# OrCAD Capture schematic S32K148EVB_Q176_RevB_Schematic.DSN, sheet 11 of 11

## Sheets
11 09. I/O HEADERS: size D; company: Freescale Semiconductor; note: SCH-29642 PDF: SPF-29642
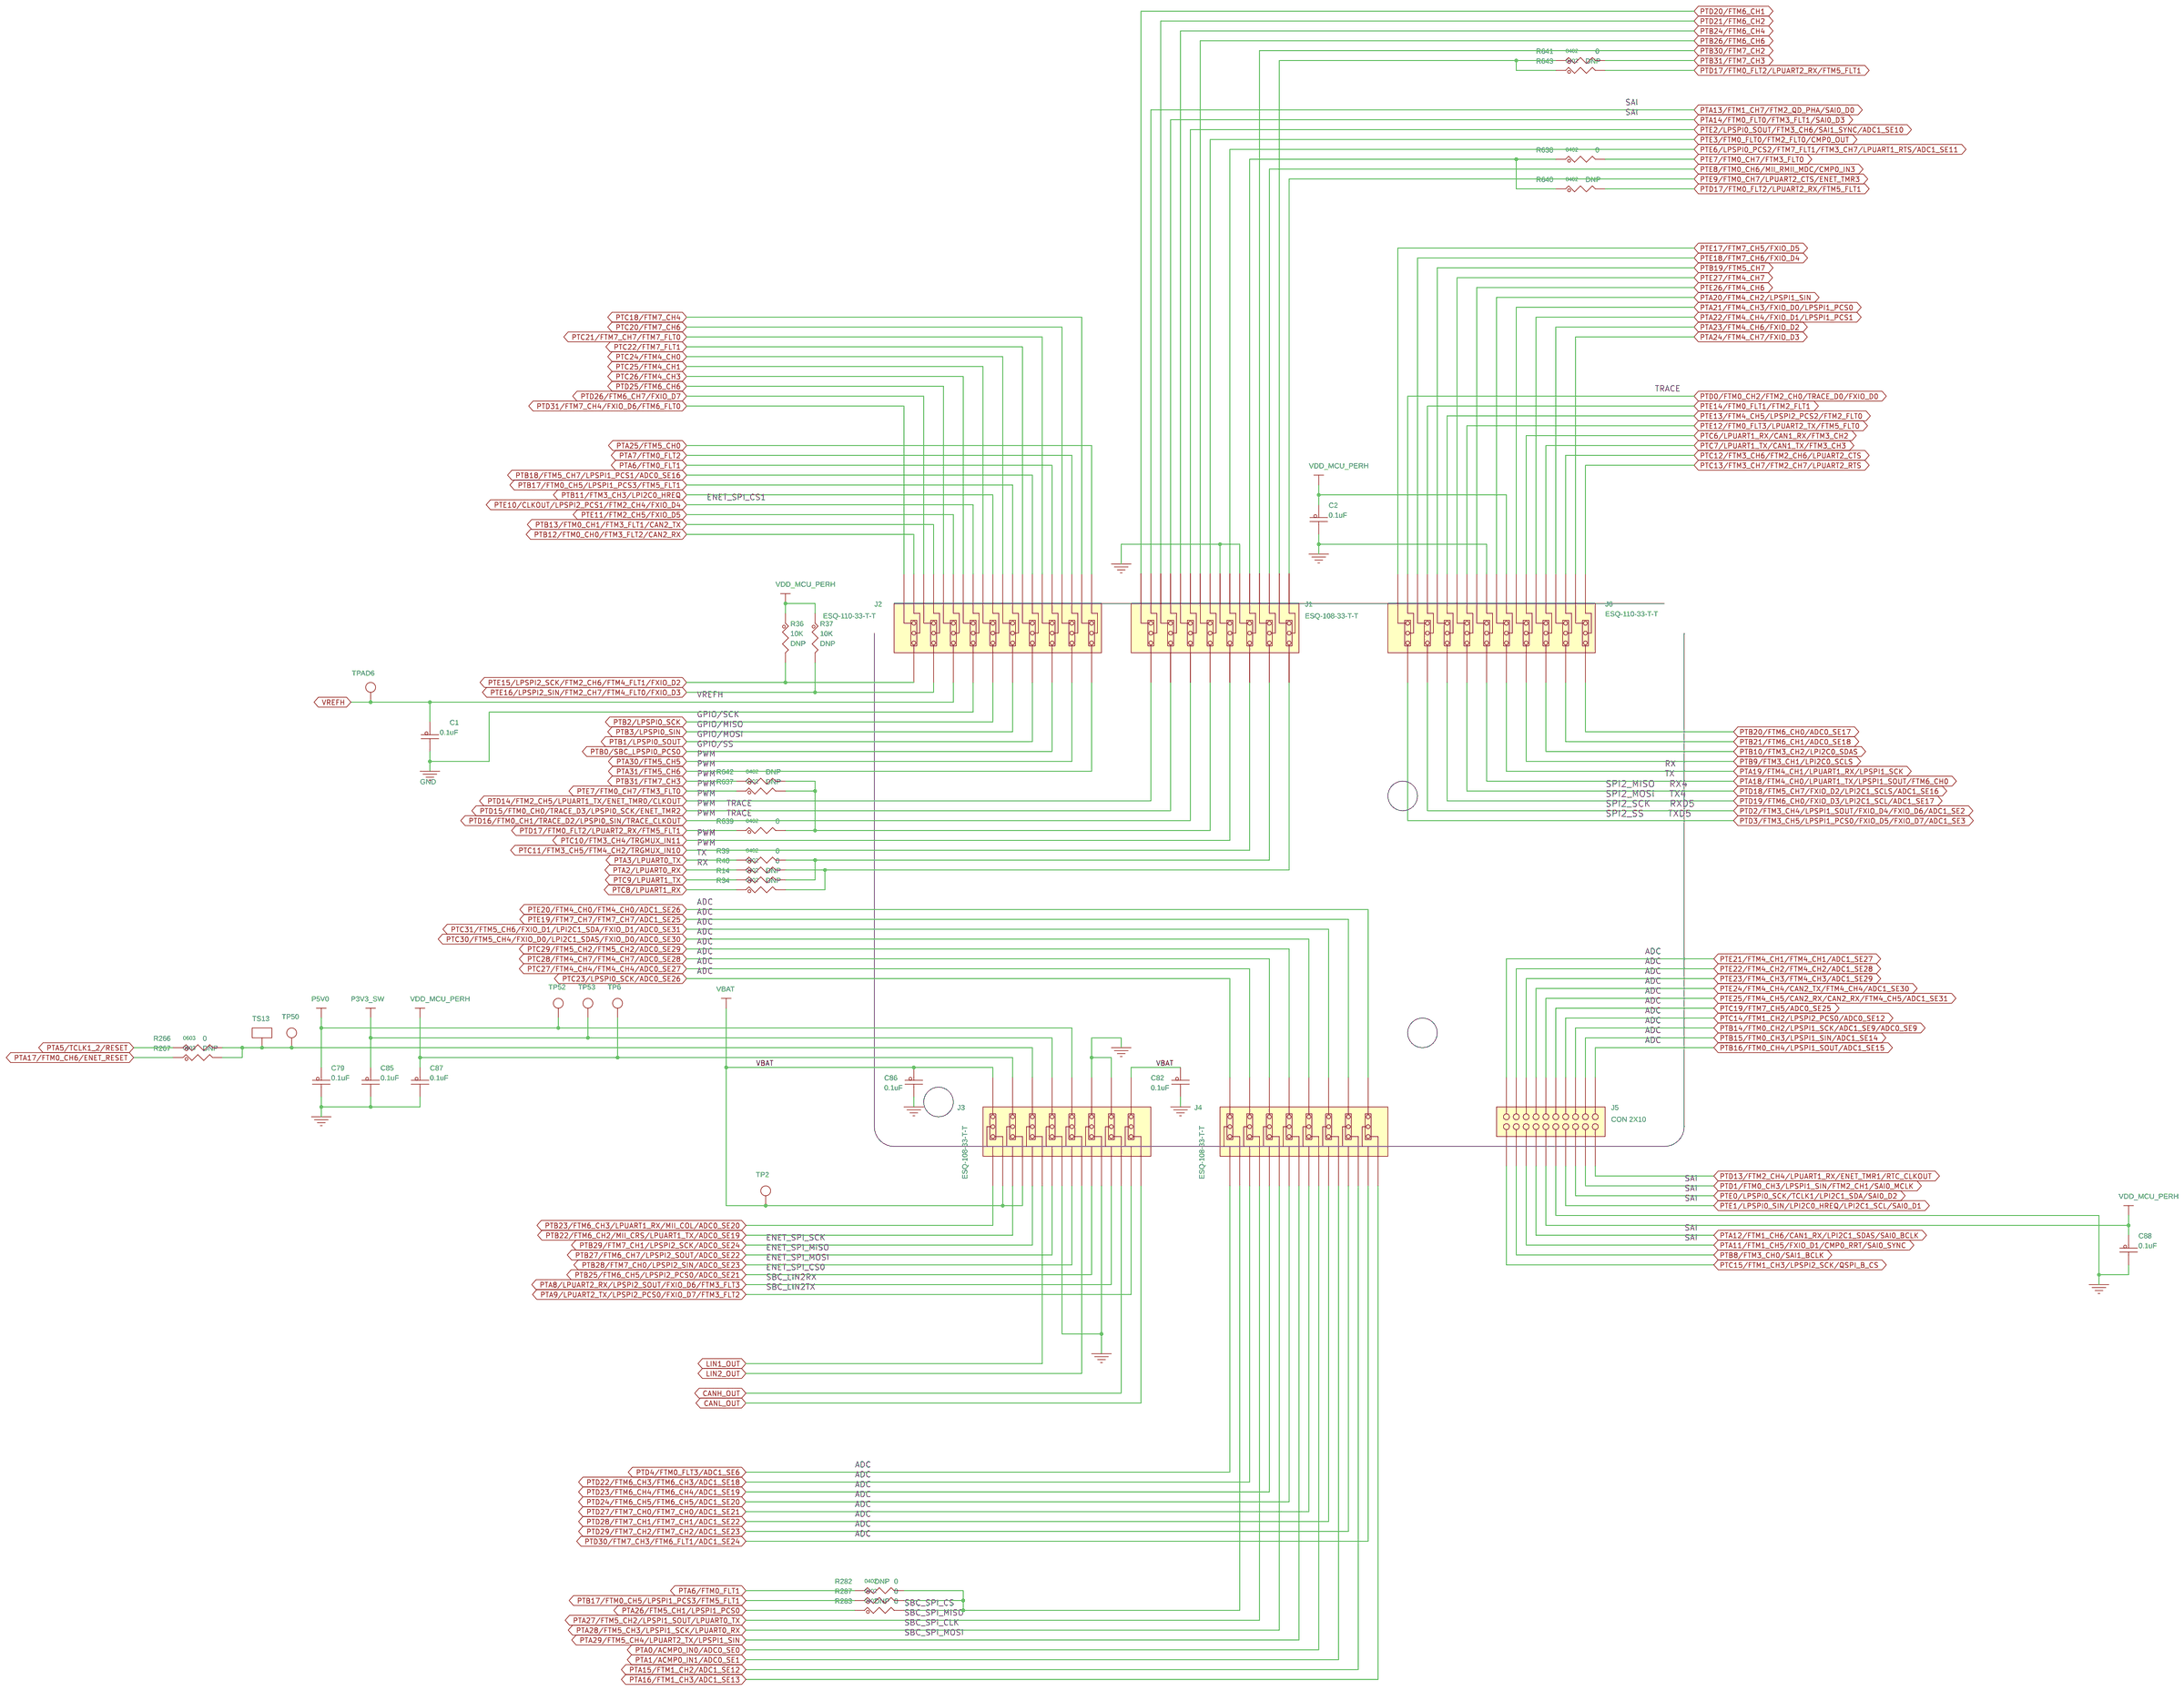
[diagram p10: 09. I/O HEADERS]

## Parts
C1  0.1uF  [CC0402_25]
C2  0.1uF  [CC0402_25]
C79  0.1uF  [CC0402_25]
C82  0.1uF  [CC0402_25]
C85  0.1uF  [CC0402_25]
C86  0.1uF  [CC0402_25]
C87  0.1uF  [CC0402_25]
C88  0.1uF  [CC0402_25]
J1  ESQ-108-33-T-T  [con_3x8_100_th]
J2  ESQ-110-33-T-T  [con_3x10_100_th]
J3  ESQ-108-33-T-T  [con_3x8_100_th]
J4  ESQ-108-33-T-T  [con_3x8_100_th]
J5  CON 2X10  [hdr210_esq_skt]
J6  ESQ-110-33-T-T  [con_3x10_100_th]
R14  0  [RC0402_25]
R34  0  [RC0402_25]
R36  10K  [RC0603_OV]
R37  10K  [RC0603_OV]
R39  0  [RC0402_25]
R40  0  [RC0402_25]
R266  0  [RC0603]
R267  0  [RC0603]
R282  0  [RC0402_25]
R283  0  [RC0402_25]
R287  0  [RC0402_25]
R637  0  [RC0402_25]
R638  0  [RC0402_25]
R639  0  [RC0402_25]
R640  0  [RC0402_25]
R641  0  [RC0402_25]
R642  0  [RC0402_25]
R643  0  [RC0402_25]
TP2  TPAD_028  [TPAD_028]
TP6  TPAD_028  [TPAD_028]
TP50  TPAD_028  [TPAD_028]
TP52  TPAD_028  [TPAD_028]
TP53  TPAD_028  [TPAD_028]
TPAD6  TPAD_030  [TPAD_030]
TS13  TESTLOOP  [testpoint_135_070mil]

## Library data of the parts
C1 C2 C79 C82 C85-C88 = CAP_NP: CAP CER 0.1uF 50V 10% X7R 0402; AGILE_PN: 150-79069; CAD_APPROVED: Yes; FPLIST: CC0402_25,CC0402_HD,0402_CC; HEIGHT: 0.55MM; MFG_NAME01: MURATA; MFG_PN01: GRM155R71H104KE14D; ROHS: Yes; Tolerance: 10%; VOLTAGE: 50V
J1 J3 J4 = HDR-3X8_A: CON 3X8 SKT TH 100MIL CTR 640H SN 90L; AGILE_PN: 210-81399; CAD_APPROVED: Yes; HEIGHT: 16.256MM; MFG_NAME01: SAMTEC; ROHS: Yes; Temp_Range: -55C to +105C
J2 J6 = HDR-3X10_A: CON 3X10 SKT TH 100MIL CTR 640H SN 90L; AGILE_PN: 210-81402; CAD_APPROVED: Yes; HEIGHT: 16/256MM; MFG_NAME01: SAMTEC; ROHS: Yes; Temp_Range: -55C to +105C
J5 = CONN_HDR_10X2: CON 2X10 SKT TH 100MIL CTR 645H SN 90L; AGILE_PN: 210-81129; CAD_APPROVED: Yes; HEIGHT: 16.38 MM; MFG_NAME01: SAMTEC; MFG_PN01: ESQ-110-33-T-D; ROHS: Yes
R14 R34 R282 R283 R637 R640 R642 R643 = RES: RES MF ZERO OHM 1/16W -- AEC-Q200 0402; AGILE_PN: 470-80742; ASSY_OPT: DNP; CAD_APPROVED: Yes; FPLIST: RC0402_25,RC0402_HD,0402_CC; HEIGHT: 0.45 MM; MFG_NAME01: VISHAY INTERTECHNOLOGY; MFG_PN01: CRCW04020000Z0ED; PCKG: 0402; ROHS: Yes
R36 R37 = RES: RES MF 10K 1/10W 5% 0603; AGILE_PN: 470-75410; ASSY_OPT: DNP; CAD_APPROVED: Yes; FPLIST: RC0603_OV,RC0603,0603_CC; HEIGHT: 0.55MM; MFG_NAME01: BOURNS; MFG_PN01: CR0603-JW-103ELF; ROHS: Yes; Tolerance: 5%
R39 R40 R287 R638 R639 R641 = RES: RES MF ZERO OHM 1/16W -- AEC-Q200 0402; AGILE_PN: 470-80742; CAD_APPROVED: Yes; FPLIST: RC0402_25,RC0402_HD,0402_CC; HEIGHT: 0.45 MM; MFG_NAME01: VISHAY INTERTECHNOLOGY; MFG_PN01: CRCW04020000Z0ED; PCKG: 0402; ROHS: Yes
R266 = RES: RES MF ZERO OHM 1/10W -- AEC-Q200 0603; AGILE_PN: 470-75407; CAD_APPROVED: Yes; FPLIST: RC0603_OV,RC0603,R603-X2,0603_CC; HEIGHT: 0.6MM; MFG_NAME01: PANASONIC; MFG_PN01: ERJ-3GEY0R00V; PCKG: 0603; ROHS: Yes; Tolerance: 1%
R267 = RES: RES MF ZERO OHM 1/10W -- AEC-Q200 0603; AGILE_PN: 470-75407; ASSY_OPT: DNP; CAD_APPROVED: Yes; FPLIST: RC0603_OV,RC0603,R603-X2,0603_CC; HEIGHT: 0.6MM; MFG_NAME01: PANASONIC; MFG_PN01: ERJ-3GEY0R00V; PCKG: 0603; ROHS: Yes; Tolerance: 1%
TP2 TP6 TP50 TP52 TP53 = TESTLOOP: TEST POINT PAD 28MIL DIA SMT, NO PART TO ORDER; AGILE_PN: 211-79313; CAD_APPROVED: Yes; HEIGHT: 0.1 MM; MFG_NAME01: N/A; MFG_PN01: N/A; ROHS: Yes
TPAD6 = TestLoop: TEST POINT PAD 30MIL DIA SMT, NO PART TO ORDER; AGILE_PN: 211-76642; CAD_APPROVED: Yes; HEIGHT: 0.1MM; MFG_NAME01: NOTACOMPONENT; MFG_PN01: NOTACOMPONENT; ROHS: Yes
TS13 = TEST_POINT_4: TEST POINT PAD SIZE 3.4MM X 1.8MM SMT; AGILE_PN: 211-75906; CAD_APPROVED: Yes; HEIGHT: 1.53 MM; MFG_NAME01: KEYSTONE ELECTRONICS; MFG_PN01: 5015; PRIORITY_PN: 922-00014; ROHS: Yes

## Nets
GND: C1.2 C2.2 C79.2 C82.2 C85.2 C86.2 C87.2 C88.2 J1.9 J1.12 J2.19 J3.12 J3.16 J3.18 J3.19 J5.12 J6.17 ; also on sheet 1 2 3 4 5 6 7 8 9
P3V3_SW: C85.1 J3.10 TP53.1(Pin1) ; also on sheet 1 2 4 5 6 7
P5V0: C79.1 J3.13 TP52.1(Pin1) ; also on sheet 1 2 4 6 9
VBAT: C82.1 C86.1 J3.1 J3.3 J3.6 J3.22 TP2.1(Pin1) ; also on sheet 2
VDD_MCU_PERH: C2.1 C87.1 C88.1 J3.4 J5.10 J6.14 R36.1 R37.1 TP6.1(Pin1) ; also on sheet 2 3 4 6 9
CANH_OUT: J3.21 ; also on sheet 2
CANL_OUT: J3.24 ; also on sheet 2
LIN1_OUT: J3.9 ; also on sheet 2
LIN2_OUT: J3.15 ; also on sheet 2
PTA0/ACMP0_IN0/ADC0_SE0: J4.15 ; also on sheet 3
PTA1/ACMP0_IN1/ADC0_SE1: J4.18 ; also on sheet 3
PTA2/LPUART0_RX: R40.1 ; also on sheet 2 3
PTA3/LPUART0_TX: R39.1 ; also on sheet 2 3
PTA5/TCLK1_2/RESET: R266.1 ; also on sheet 2 3 4 5
PTA6/FTM0_FLT1: J2.8 R282.1 ; also on sheet 3
PTA7/FTM0_FLT2: J2.5 ; also on sheet 3
PTA8/LPUART2_RX/LPSPI2_SOUT/FXIO_D6/FTM3_FLT3: J3.20 ; also on sheet 2 3
PTA9/LPUART2_TX/LPSPI2_PCS0/FXIO_D7/FTM3_FLT2: J3.23 ; also on sheet 2 3
PTA11/FTM1_CH5/FXIO_D1/CMP0_RRT/SAI0_SYNC: J5.6 ; also on sheet 1 3
PTA12/FTM1_CH6/CAN1_RX/LPI2C1_SDAS/SAI0_BCLK: J5.8 ; also on sheet 1 3
PTA13/FTM1_CH7/FTM2_QD_PHA/SAI0_D0: J1.23 ; also on sheet 1 3
PTA14/FTM0_FLT0/FTM3_FLT1/SAI0_D3: J1.20 ; also on sheet 1 3
PTA15/FTM1_CH2/ADC1_SE12: J4.21 ; also on sheet 3
PTA16/FTM1_CH3/ADC1_SE13: J4.24 ; also on sheet 3
PTA17/FTM0_CH6/ENET_RESET: R267.1 ; also on sheet 3 4
PTA18/FTM4_CH0/LPUART1_TX/LPSPI1_SOUT/FTM6_CH0: J6.16 ; also on sheet 3
PTA19/FTM4_CH1/LPUART1_RX/LPSPI1_SCK: J6.13 ; also on sheet 3
PTA20/FTM4_CH2/LPSPI1_SIN: J6.15 ; also on sheet 3
PTA21/FTM4_CH3/FXIO_D0/LPSPI1_PCS0: J6.12 ; also on sheet 3
PTA22/FTM4_CH4/FXIO_D1/LPSPI1_PCS1: J6.9 ; also on sheet 3
PTA23/FTM4_CH6/FXIO_D2: J6.6 ; also on sheet 3
PTA24/FTM4_CH7/FXIO_D3: J6.3 ; also on sheet 3
PTA25/FTM5_CH0: J2.2 ; also on sheet 3 4
PTA26/FTM5_CH1/LPSPI1_PCS0: R283.1 ; also on sheet 2 3
PTA27/FTM5_CH2/LPSPI1_SOUT/LPUART0_TX: J4.6 ; also on sheet 2 3
PTA28/FTM5_CH3/LPSPI1_SCK/LPUART0_RX: J4.9 ; also on sheet 2 3
PTA29/FTM5_CH4/LPUART2_TX/LPSPI1_SIN: J4.12 ; also on sheet 2 3
PTA30/FTM5_CH5: J2.4 ; also on sheet 3
PTA31/FTM5_CH6: J2.1 ; also on sheet 3
PTB0/SBC_LPSPI0_PCS0: J2.7 ; also on sheet 3
PTB1/LPSPI0_SOUT: J2.10 ; also on sheet 3
PTB2/LPSPI0_SCK: J2.16 ; also on sheet 3
PTB3/LPSPI0_SIN: J2.13 ; also on sheet 3
PTB8/FTM3_CH0/SAI1_BCLK: J5.4 ; also on sheet 1 3
PTB9/FTM3_CH1/LPI2C0_SCLS: J6.10 ; also on sheet 1 3 6
PTB10/FTM3_CH2/LPI2C0_SDAS: J6.7 ; also on sheet 1 3 6
PTB11/FTM3_CH3/LPI2C0_HREQ: J2.17 ; also on sheet 3
PTB12/FTM0_CH0/FTM3_FLT2/CAN2_RX: J2.29 ; also on sheet 3
PTB13/FTM0_CH1/FTM3_FLT1/CAN2_TX: J2.26 ; also on sheet 3
PTB14/FTM0_CH2/LPSPI1_SCK/ADC1_SE9/ADC0_SE9: J5.15 ; also on sheet 3
PTB15/FTM0_CH3/LPSPI1_SIN/ADC1_SE14: J5.17 ; also on sheet 3
PTB16/FTM0_CH4/LPSPI1_SOUT/ADC1_SE15: J5.19 ; also on sheet 3
PTB17/FTM0_CH5/LPSPI1_PCS3/FTM5_FLT1: J2.14 R287.1 ; also on sheet 3
PTB18/FTM5_CH7/LPSPI1_PCS1/ADC0_SE16: J2.11 ; also on sheet 3
PTB19/FTM5_CH7: J6.24 ; also on sheet 3
PTB20/FTM6_CH0/ADC0_SE17: J6.1 ; also on sheet 3 4
PTB21/FTM6_CH1/ADC0_SE18: J6.4 ; also on sheet 3
PTB22/FTM6_CH2/MII_CRS/LPUART1_TX/ADC0_SE19: J3.5 ; also on sheet 3
PTB23/FTM6_CH3/LPUART1_RX/MII_COL/ADC0_SE20: J3.2 ; also on sheet 3
PTB24/FTM6_CH4: J1.18 ; also on sheet 3
PTB25/FTM6_CH5/LPSPI2_PCS0/ADC0_SE21: J3.17 ; also on sheet 3 6
PTB26/FTM6_CH6: J1.15 ; also on sheet 3
PTB27/FTM6_CH7/LPSPI2_SOUT/ADC0_SE22: J3.11 ; also on sheet 3 6
PTB28/FTM7_CH0/LPSPI2_SIN/ADC0_SE23: J3.14 ; also on sheet 3 6
PTB29/FTM7_CH1/LPSPI2_SCK/ADC0_SE24: J3.8 ; also on sheet 3 6
PTB30/FTM7_CH2: J1.6 ; also on sheet 3
PTB31/FTM7_CH3: R641.2 R642.1 ; also on sheet 3
PTC6/LPUART1_RX/CAN1_RX/FTM3_CH2: J6.11 ; also on sheet 3 5
PTC7/LPUART1_TX/CAN1_TX/FTM3_CH3: J6.8 ; also on sheet 3 5
PTC8/LPUART1_RX: R34.1 ; also on sheet 3 5
PTC9/LPUART1_TX: R14.1 ; also on sheet 3 5
PTC10/FTM3_CH4/TRGMUX_IN11: J1.10 ; also on sheet 3
PTC11/FTM3_CH5/FTM4_CH2/TRGMUX_IN10: J1.7 ; also on sheet 3
PTC12/FTM3_CH6/FTM2_CH6/LPUART2_CTS: J6.5 ; also on sheet 3
PTC13/FTM3_CH7/FTM2_CH7/LPUART2_RTS: J6.2 ; also on sheet 3
PTC14/FTM1_CH2/LPSPI2_PCS0/ADC0_SE12: J5.13 ; also on sheet 3
PTC15/FTM1_CH3/LPSPI2_SCK/QSPI_B_CS: J5.2 ; also on sheet 3
PTC18/FTM7_CH4: J2.3 ; also on sheet 3
PTC19/FTM7_CH5/ADC0_SE25: J5.11 ; also on sheet 3
PTC20/FTM7_CH6: J2.6 ; also on sheet 3
PTC21/FTM7_CH7/FTM7_FLT0: J2.9 ; also on sheet 3
PTC22/FTM7_FLT1: J2.12 ; also on sheet 3
PTC23/LPSPI0_SCK/ADC0_SE26: J4.1 ; also on sheet 3
PTC24/FTM4_CH0: J2.15 ; also on sheet 3
PTC25/FTM4_CH1: J2.18 ; also on sheet 3
PTC26/FTM4_CH3: J2.21 ; also on sheet 3
PTC27/FTM4_CH4/FTM4_CH4/ADC0_SE27: J4.4 ; also on sheet 3
PTC28/FTM4_CH7/FTM4_CH7/ADC0_SE28: J4.7 ; also on sheet 3
PTC29/FTM5_CH2/FTM5_CH2/ADC0_SE29: J4.10 ; also on sheet 3
PTC30/FTM5_CH4/FXIO_D0/LPI2C1_SDAS/FXIO_D0/ADC0_SE30: J4.13 ; also on sheet 1 3
PTC31/FTM5_CH6/FXIO_D1/LPI2C1_SDA/FXIO_D1/ADC0_SE31: J4.16 ; also on sheet 1 3
PTD0/FTM0_CH2/FTM2_CH0/TRACE_D0/FXIO_D0: J6.29 ; also on sheet 3
PTD1/FTM0_CH3/LPSPI1_SIN/FTM2_CH1/SAI0_MCLK: J5.18 ; also on sheet 1 3
PTD2/FTM3_CH4/LPSPI1_SOUT/FXIO_D4/FXIO_D6/ADC1_SE2: J6.25 ; also on sheet 3
PTD3/FTM3_CH5/LPSPI1_PCS0/FXIO_D5/FXIO_D7/ADC1_SE3: J6.28 ; also on sheet 3
PTD4/FTM0_FLT3/ADC1_SE6: J4.2 ; also on sheet 3
PTD13/FTM2_CH4/LPUART1_RX/ENET_TMR1/RTC_CLKOUT: J5.20 ; also on sheet 1 3
PTD14/FTM2_CH5/LPUART1_TX/ENET_TMR0/CLKOUT: J1.22 ; also on sheet 1 3
PTD15/FTM0_CH0/TRACE_D3/LPSPI0_SCK/ENET_TMR2: J1.19 ; also on sheet 1 3
PTD16/FTM0_CH1/TRACE_D2/LPSPI0_SIN/TRACE_CLKOUT: J1.16 ; also on sheet 3
PTD17/FTM0_FLT2/LPUART2_RX/FTM5_FLT1: R639.1 R640.2 R643.2 ; also on sheet 3
PTD18/FTM5_CH7/FXIO_D2/LPI2C1_SCLS/ADC1_SE16: J6.19 ; also on sheet 1 3
PTD19/FTM6_CH0/FXIO_D3/LPI2C1_SCL/ADC1_SE17: J6.22 ; also on sheet 1 3
PTD20/FTM6_CH1: J1.24 ; also on sheet 3
PTD21/FTM6_CH2: J1.21 ; also on sheet 3
PTD22/FTM6_CH3/FTM6_CH3/ADC1_SE18: J4.5 ; also on sheet 3
PTD23/FTM6_CH4/FTM6_CH4/ADC1_SE19: J4.8 ; also on sheet 3
PTD24/FTM6_CH5/FTM6_CH5/ADC1_SE20: J4.11 ; also on sheet 3
PTD25/FTM6_CH6: J2.24 ; also on sheet 3
PTD26/FTM6_CH7/FXIO_D7: J2.27 ; also on sheet 3
PTD27/FTM7_CH0/FTM7_CH0/ADC1_SE21: J4.14 ; also on sheet 3
PTD28/FTM7_CH1/FTM7_CH1/ADC1_SE22: J4.17 ; also on sheet 3
PTD29/FTM7_CH2/FTM7_CH2/ADC1_SE23: J4.20 ; also on sheet 3 6
PTD30/FTM7_CH3/FTM6_FLT1/ADC1_SE24: J4.23 ; also on sheet 3
PTD31/FTM7_CH4/FXIO_D6/FTM6_FLT0: J2.30 ; also on sheet 3
PTE0/LPSPI0_SCK/TCLK1/LPI2C1_SDA/SAI0_D2: J5.16 ; also on sheet 1 3
PTE1/LPSPI0_SIN/LPI2C0_HREQ/LPI2C1_SCL/SAI0_D1: J5.14 ; also on sheet 1 3
PTE2/LPSPI0_SOUT/FTM3_CH6/SAI1_SYNC/ADC1_SE10: J1.17 ; also on sheet 1 3
PTE3/FTM0_FLT0/FTM2_FLT0/CMP0_OUT: J1.14 ; also on sheet 3
PTE6/LPSPI0_PCS2/FTM7_FLT1/FTM3_CH7/LPUART1_RTS/ADC1_SE11: J1.11 ; also on sheet 3
PTE7/FTM0_CH7/FTM3_FLT0: R637.1 R638.2 ; also on sheet 3
PTE8/FTM0_CH6/MII_RMII_MDC/CMP0_IN3: J1.5 ; also on sheet 3
PTE9/FTM0_CH7/LPUART2_CTS/ENET_TMR3: J1.2 ; also on sheet 1 3
PTE10/CLKOUT/LPSPI2_PCS1/FTM2_CH4/FXIO_D4: J2.20 ; also on sheet 1 3 6
PTE11/FTM2_CH5/FXIO_D5: J2.23 ; also on sheet 1 3
PTE12/FTM0_FLT3/LPUART2_TX/FTM5_FLT0: J6.20 ; also on sheet 3
PTE13/FTM4_CH5/LPSPI2_PCS2/FTM2_FLT0: J6.23 ; also on sheet 3 6
PTE14/FTM0_FLT1/FTM2_FLT1: J6.26 ; also on sheet 3
PTE15/LPSPI2_SCK/FTM2_CH6/FTM4_FLT1/FXIO_D2: J2.28 R36.2 ; also on sheet 1 3
PTE16/LPSPI2_SIN/FTM2_CH7/FTM4_FLT0/FXIO_D3: J2.25 R37.2 ; also on sheet 1 3
PTE17/FTM7_CH5/FXIO_D5: J6.30 ; also on sheet 3
PTE18/FTM7_CH6/FXIO_D4: J6.27 ; also on sheet 3
PTE19/FTM7_CH7/FTM7_CH7/ADC1_SE25: J4.19 ; also on sheet 2 3
PTE20/FTM4_CH0/FTM4_CH0/ADC1_SE26: J4.22 ; also on sheet 2 3
PTE21/FTM4_CH1/FTM4_CH1/ADC1_SE27: J5.1 ; also on sheet 3
PTE22/FTM4_CH2/FTM4_CH2/ADC1_SE28: J5.3 ; also on sheet 3
PTE23/FTM4_CH3/FTM4_CH3/ADC1_SE29: J5.5 ; also on sheet 3
PTE24/FTM4_CH4/CAN2_TX/FTM4_CH4/ADC1_SE30: J5.7 ; also on sheet 3
PTE25/FTM4_CH5/CAN2_RX/CAN2_RX/FTM4_CH5/ADC1_SE31: J5.9 ; also on sheet 3
PTE26/FTM4_CH6: J6.18 ; also on sheet 3
PTE27/FTM4_CH7: J6.21 ; also on sheet 3
VREFH: C1.1 J2.22 TPAD6.1(Pin1) ; also on sheet 3
N16920480: J1.8 R638.1 R640.1
N17147847: J3.7 R266.2 R267.2 TP50.1(Pin1) TS13.1
N17164200: J1.1 R34.2 R40.2
N17164202: J1.4 R14.2 R39.2
N17164208: J1.13 R637.2 R639.2 R642.2
N17330326: J4.3 R282.2 R283.2 R287.2
N17376978: J1.3 R641.1 R643.1

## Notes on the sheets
sheet 11
- SAI
- SAI
- TRACE
- ENET_SPI_CS1
- VREFH
- GPIO/SCK
- GPIO/MISO
- GPIO/MOSI
- GPIO/SS
- PWM
- PWM
- RX
- PWM
- TX
- PWM
- SPI2_MISO   RX4
- PWM
- SPI2_MOSI   TX4
- PWM
- TRACE
- SPI2_SCK    RXD5
- PWM
- TRACE
- SPI2_SS     TXD5
- PWM
- PWM
- PWM
- TX
- RX
- ADC
- ADC
- ADC
- ADC
- ADC
- ADC
- ADC
- ADC
- ADC
- ADC
- ADC
- ADC
- ADC
- ADC
- ADC
- ADC
- ADC
- ADC
- SAI
- SAI
- SAI
- SAI
- ENET_SPI_SCK
- SAI
- ENET_SPI_MISO
- ENET_SPI_MOSI
- ENET_SPI_CS0
- SBC_LIN2RX
- SBC_LIN2TX
- ADC
- ADC
- ADC
- ADC
- ADC
- ADC
- ADC
- ADC
- SBC_SPI_CS
- SBC_SPI_MISO
- SBC_SPI_CLK
- SBC_SPI_MOSI
